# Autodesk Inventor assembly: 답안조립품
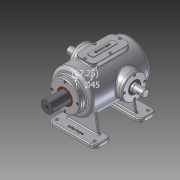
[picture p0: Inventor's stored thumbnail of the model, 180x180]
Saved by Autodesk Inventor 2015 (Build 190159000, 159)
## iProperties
Created: 2016-02
Part Number: 답안조립품
Document SubType Name: Assembly
Designer: Administrator
Mass: 8191.33 g
Surface Area: 4241.84 cm^2
Volume: 1855.51 cm^3
Density: 4.41461 g/cm^3
Author: Administrator
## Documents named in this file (15)
- C:\Users\Administrator\Desktop\360220V1005\답안조립품.iam
- C:\Users\Administrator\Desktop\360220V1005\본체.ipt
- C:\Users\Administrator\Desktop\360220V1005\슬라이드 커버.ipt
- C:\Users\Administrator\Desktop\360220V1005\부시.ipt
- C:\Users\Administrator\Desktop\360220V1005\볼트 M4x0.7.ipt
- C:\Users\Administrator\Desktop\360220V1005\상부커버.ipt
- C:\Users\Administrator\Desktop\360220V1005\육각머리볼트 M4.ipt
- C:\Users\Administrator\Desktop\360220V1005\베어링 6205.ipt
- 베어링 6205.ipt
- C:\Users\Administrator\Desktop\360220V1005\축 커버.ipt
- C:\Users\Administrator\Desktop\360220V1005\편심축.ipt
- C:\Users\Administrator\Desktop\360220V1005\오일실.ipt
- 오일실.ipt
- C:\Users\Administrator\Desktop\360220V1005\슬라이드.ipt
- C:\Users\Administrator\Desktop\360220V1005\가변스프링.ipt
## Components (13 placed, 2 different names)
1. 가변스프링:1
2. M4x0.7:1
3. M4x0.7:2
4. M4x0.7:3
5. M4x0.7:4
6. M4x0.7:5
7. M4x0.7:6
8. M4x0.7:7
9. M4x0.7:8
10. M4x0.7:9
11. M4x0.7:10
12. M4x0.7:11
13. M4x0.7:12
